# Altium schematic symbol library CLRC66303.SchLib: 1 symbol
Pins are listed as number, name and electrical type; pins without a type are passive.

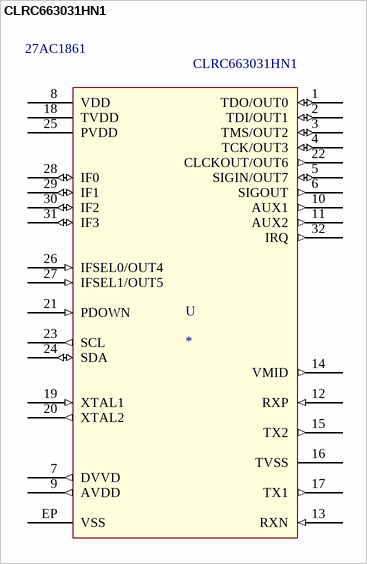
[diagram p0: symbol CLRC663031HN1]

## CLRC663031HN1
designator U  value CLRC663031HN1  Supplier Part Number 1: 27AC1861
footprint PCBComponent_1
pins: 1 TDO/OUT0 (io), 2 TDI/OUT1 (io), 3 TMS/OUT2 (io), 4 TCK/OUT3 (io), 5 SIGIN/OUT7 (io), 6 SIGOUT (out), 7 DVVD (out), 8 VDD (power), 9 AVDD (out), 10 AUX1 (out), 11 AUX2 (out), 12 RXP (in), 13 RXN (in), 14 VMID (out), 15 TX2 (out), 16 TVSS (power), 17 TX1 (out), 18 TVDD (power), 19 XTAL1 (in), 20 XTAL2 (out), 21 PDOWN (in), 22 CLCKOUT/OUT6 (out), 23 SCL (out), 24 SDA (io), 25 PVDD (power), 26 IFSEL0/OUT4 (in), 27 IFSEL1/OUT5 (in), 28 IF0 (io), 29 IF1 (io), 30 IF2 (io), 31 IF3 (io), 32 IRQ (out), EP VSS (power)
